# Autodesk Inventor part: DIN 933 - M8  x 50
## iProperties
Created: 2006-09
Part Number: DIN 933 - M8  x 50
Material: BgAAAEgAAABOAEEATQBFAFMACgBNAGEAdABlAHIAaQBhAGwAcwAKADEAOgBTAHQAZQBlAGwALAAgAE0AaQBsAGQACgAKAEUATgBEAAoAAAA=
Description: Sechskantschraube
Vendor: Autodesk Inc.
Document SubType Name: Modeling
Standard: DIN 933
Designer: ERNST
Standards Organization: DIN
Language: de-DE
Size Designation: M8  x 50
Categories: <MemberInstance Version="R10.0.0"><Categories><Category DisplayName="Schrauben" InternalName="e4da775c-781d-43d5-af7c-5136215cf5a6" Mnemonic="FSTN"><Category Di
Mass: 25.3536 g
Surface Area: 17.6629 cm^2
Volume: 3.22565 cm^3
Density: 7.86 g/cm^3
Author: ERNST
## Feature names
1. Körper [Revolution]
2. Kopf [Extrusion]
3. Fase1 [Revolution]
4. Fase2 [Chamfer]
